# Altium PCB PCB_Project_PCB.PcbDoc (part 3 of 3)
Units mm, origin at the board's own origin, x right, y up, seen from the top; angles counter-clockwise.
Board outline 185 x 95 mm, 2 copper layers (Top Layer, Bottom Layer), stack 1.575 mm thick; 173 components, 93 nets, 424 pads, 126 vias.
Unrouted connection lines stored in the file: 1.
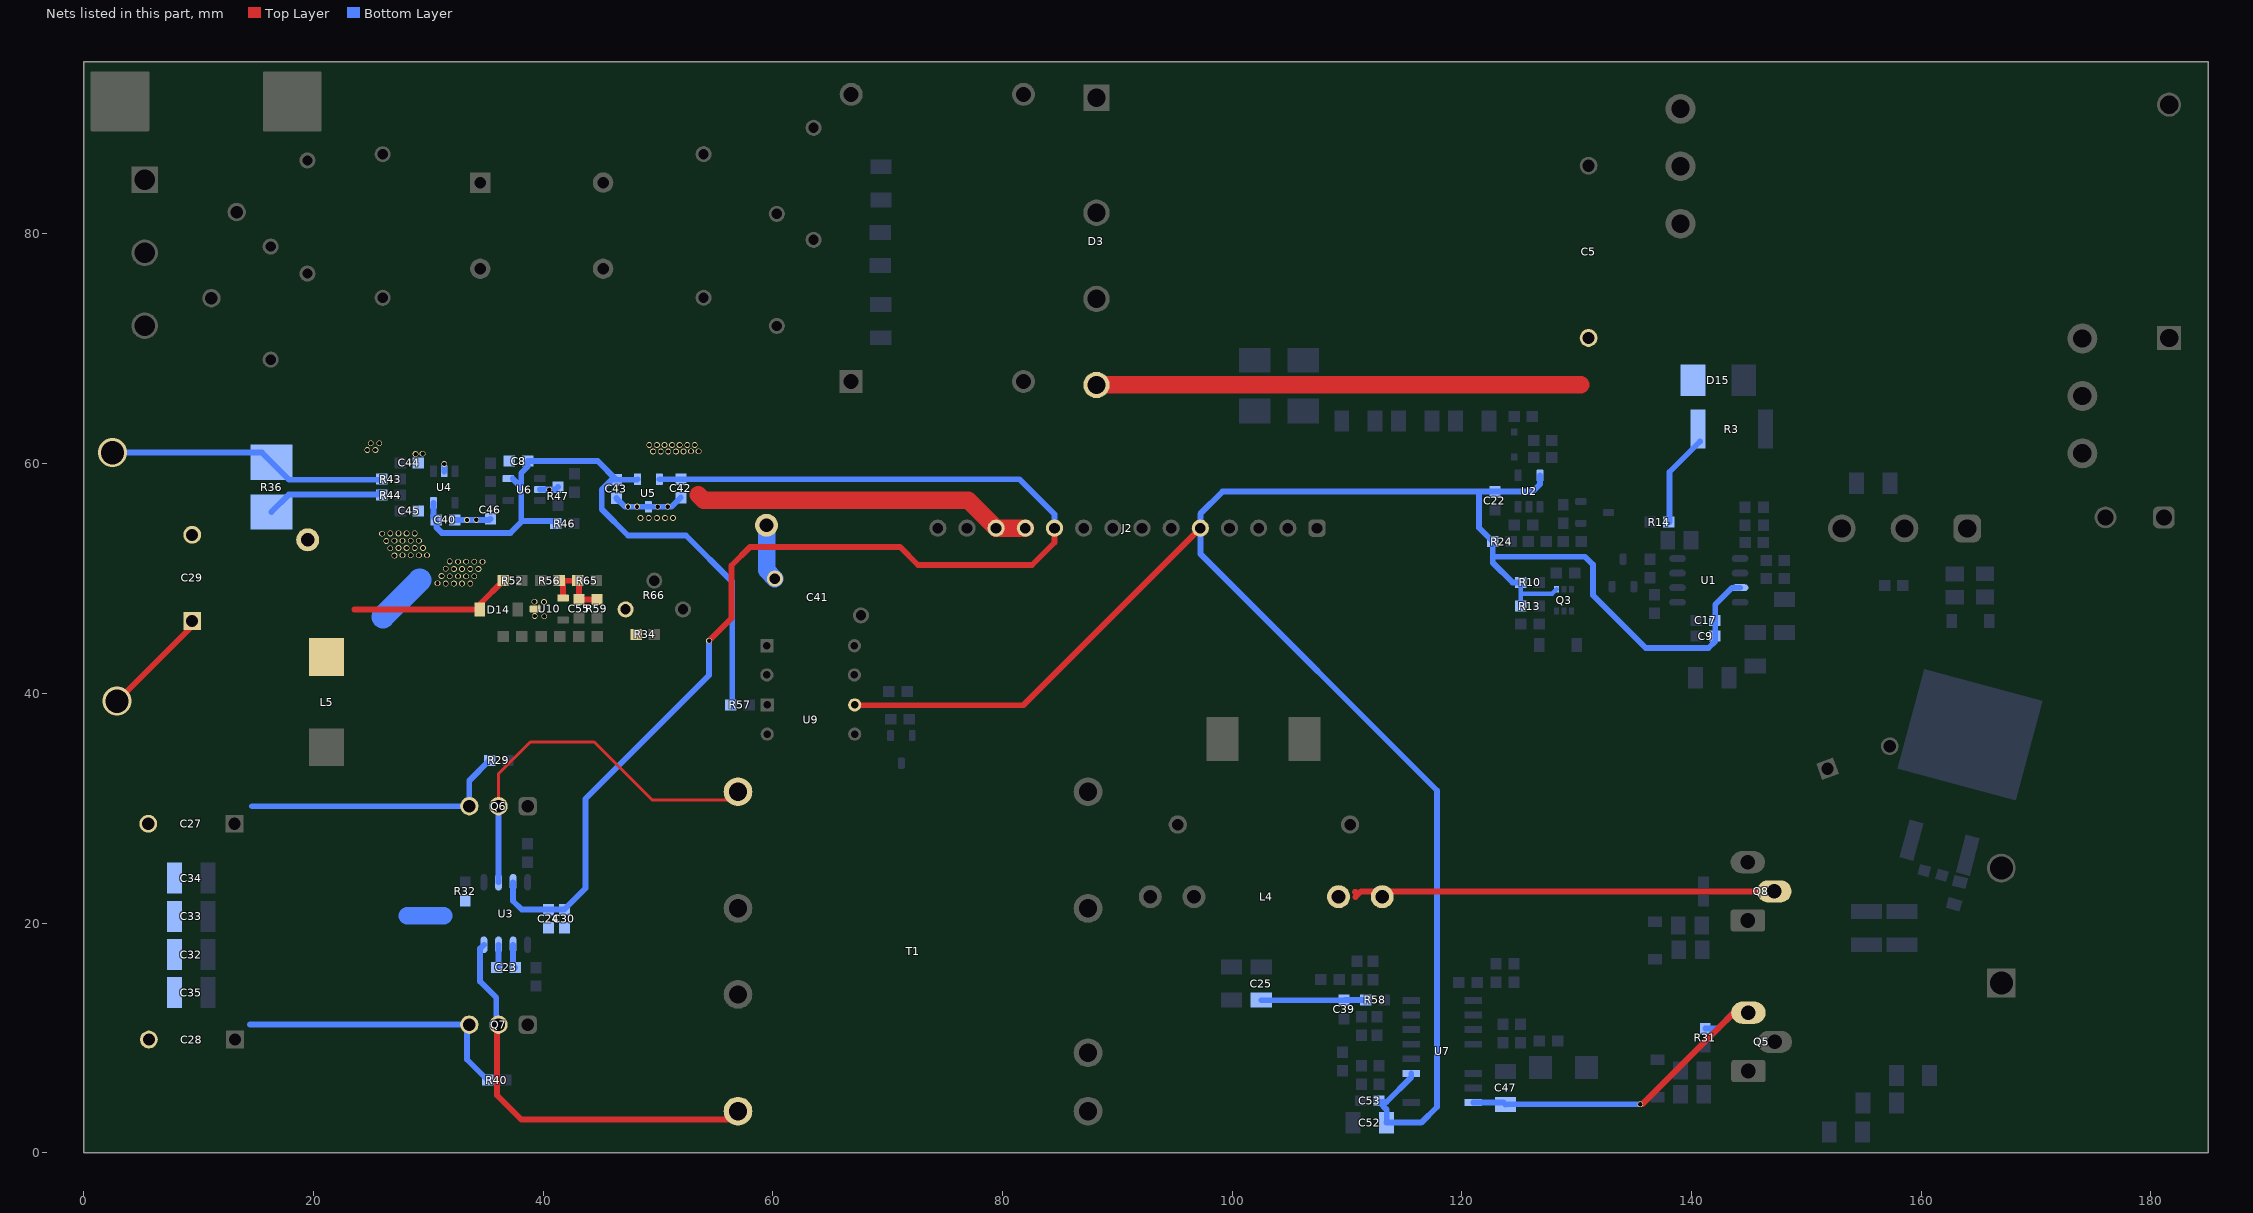
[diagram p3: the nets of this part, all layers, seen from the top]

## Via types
v1: diameter 0.508, hole 0.381, Top Layer to Bottom Layer, 124 vias
v2: diameter 2.54, hole 2.032, Top Layer to Bottom Layer, 2 vias

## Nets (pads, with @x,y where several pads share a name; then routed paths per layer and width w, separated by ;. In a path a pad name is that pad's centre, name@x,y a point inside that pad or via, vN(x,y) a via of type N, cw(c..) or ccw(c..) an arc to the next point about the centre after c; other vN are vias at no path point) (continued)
Pri_15V: C9.1 C17.1 C22.1 C52.1 C53.1 J2.5 Q3.4 R10.2 R13.2 R24.2 U1.7 U2.5 U7.3 U9.4 | length 184.7
  Top Layer w0.508: U9.4@67.142,38.964 81.813,38.964 J2.5@97.231,54.381
  Bottom Layer w0.381: R13.2@125.146,47.6 125.146,48.666 ; R10.2@125.146,49.662 125.146,48.666 ; Q3.4@128.255,49.063 127.859,48.666 125.146,48.666
  Bottom Layer w0.508: C52.1@113.439,2.616 C52.1@113.464,2.616 ; U7.3@115.592,6.909 115.592,6.575 113.436,4.42 112.789,4.42 113.464,3.744 C52.1@113.464,2.616 ; 122.695,52.019 R24.2@122.695,53.213 121.488,54.42 121.488,57.379 121.679,57.569 ; R10.2@125.146,49.662 124.404,49.662 122.695,51.371 122.695,51.892 130.734,51.892 131.42,51.206 131.42,48.539 136.017,43.942 141.478,43.942 142.075,44.539 142.075,47.739 143.535,49.199 U1.7@144.228,49.199 ; U2.5@126.807,58.982 126.807,58.202 126.174,57.569 C22.1@122.885,57.569 121.679,57.569 ; C52.1@113.464,2.616 116.459,2.616 117.831,3.988 117.831,31.547 97.231,52.146 J2.5@97.231,54.381 97.231,55.626 99.174,57.569 121.679,57.569
R_SENSE: R36.2 R43.2 | length 24.1
  Bottom Layer w0.508: v2(2.515,60.96) 15.52,60.96 R36.2@16.358,60.123 17.883,58.598 R43.2@25.654,58.598
Reg: C23.1 U3.3 | length 2
  Bottom Layer w0.508: C23.1@35.979,16.129 36.119,16.269 U3.3@36.119,18.103
Sec_3.3V: C8.1 C40.1 C43.1 R46.1 R57.2 U4.5 U5.1 U6.5 | length 58.3
  Bottom Layer w0.508: U4.5@30.444,56.575 30.444,55.357 C40.1@30.696,55.105 30.696,54.457 31.178,53.975 37.16,53.975 38.1,54.915 ; U6.5@37.353,58.697 38.1,57.95 ; R46.1@41.085,54.788 40.856,55.016 38.202,55.016 38.1,54.915 ; U5.1@48.224,58.642 48.18,58.598 C43.1@46.38,58.598 ; R57.2@56.477,38.862 56.477,49.72 52.451,53.746 47.396,53.746 45.11,56.032 45.11,57.726 45.982,58.598 C43.1@46.38,58.598 ; 38.1,54.915 38.1,57.95 ; 38.1,57.95 38.1,59.182 38.671,59.753 C8.1@38.671,60.223 44.755,60.223 C43.1@46.38,58.598
Sec_15V: C24.1 C30.1 C42.1 J2.10 U3.7 U5.2 | length 110.8
  Top Layer w0.508: v1(54.458,44.577) 56.413,46.533 56.413,51.13 58.039,52.756 71.08,52.756 72.655,51.181 82.575,51.181 84.531,53.137 J2.10@84.531,54.381
  Bottom Layer w0.508: U3.7@37.389,23.553 37.389,21.92 38.138,21.171 C24.1@40.488,21.171 41.834,21.171 43.688,23.025 43.688,30.81 54.458,41.58 v1(54.458,44.577) ; U5.2@50.124,58.642 51.987,58.642 C42.1@51.994,58.648 81.483,58.648 84.531,55.601 J2.10@84.531,54.381 J2.10@84.531,54.331
SGND: C8.2 C23.2 C24.2 C27.2 C28.2 C29.2 C30.2 C32.2 C33.2 C34.2 C35.2 C40.2 C41.2 C42.2 C43.2 C44.2 C45.2 C46.2 J2.11 J2.12 pad.2 pad.3 Q6.3 Q7.3 R29.2 R32.1 R34.1 R36.1 R40.2 R44.2 R47.1 R66.1 U3.2 U4.2 U5.3 U6.2 U10.3 | length 114.3
  Top Layer w1.524: 53.518,57.302 54,56.82 77.013,56.82 J2.12@79.451,54.381 J2.11@81.991,54.381
  Bottom Layer w0.508: 14.469,11.151 33.376,11.151 33.376,8.115 R40.2@35.166,6.325 ; 14.656,30.175 Q6.3@33.579,30.175 33.579,32.398 R29.2@35.344,34.163 ; R36.1@16.358,55.803 17.857,57.302 25.527,57.302 R44.2@25.705,57.48 ; U4.2@31.394,59.325 v1(31.394,59.969) ; C40.2@32.296,55.105 v1(34.188,55.105) 35.319,55.105 C46.2@35.408,55.194 ; U3.2@37.389,18.103 37.389,16.319 C23.2@37.579,16.129 ; U6.2@39.729,57.747 41.085,57.747 R47.1@41.3,57.963 ; C43.2@46.38,56.998 47.136,56.242 U5.3@49.174,56.242 v1(49.987,56.242) 51.187,56.242 C42.2@51.994,57.048
  Bottom Layer w1.524: 28.157,20.625 31.344,20.625 ; pad.2@59.461,54.635 59.461,50.707 C41.2@60.182,49.987
  Bottom Layer w2.007: 26.06,46.66 29.261,49.86
  other v1: 40.107,46.711 39.268,46.736 40.081,47.955 39.243,47.981 31.521,49.555 32.233,49.555 32.944,49.555 33.655,49.555 30.81,49.581 31.877,50.19 32.588,50.19 33.299,50.19 34.011,50.19 31.166,50.216 32.233,50.825 32.944,50.825 33.655,50.825 34.366,50.825 31.521,50.851 32.588,51.46 33.299,51.46 34.011,51.46 34.722,51.46 31.877,51.486 27.051,51.994 27.762,52.019 28.473,52.019 29.185,52.019 29.896,52.019 26.695,52.629 27.407,52.654 28.118,52.654 28.829,52.654 29.54,52.654 26.34,53.264 27.051,53.289 27.762,53.289 28.473,53.289 29.185,53.289 25.984,53.899 26.695,53.924 27.407,53.924 28.118,53.924 28.829,53.924 33.376,55.093 48.489,55.27 49.2,55.27 49.911,55.27 50.622,55.27 51.308,55.27 47.396,56.261 48.184,56.261 50.851,56.261 40.538,57.734 28.905,60.833 29.515,60.858 49.581,61.062 50.241,61.062 50.902,61.062 51.562,61.062 52.222,61.062 52.883,61.087 53.543,61.087 24.689,61.189 25.4,61.189 49.251,61.62 49.911,61.62 50.571,61.62 51.232,61.62 51.892,61.62 52.553,61.62 53.213,61.62 24.994,61.773 25.73,61.773
SW: C47.2 L4.1 Q5.3 Q8.2 R31.1 U7.16 | length 68.4
  Top Layer w0.508: 110.681,22.714 110.76,22.723 ; 110.735,22.266 111.227,22.758 Q8.2@147.207,22.758 ; v1(135.534,4.216) 135.712,4.216 143.688,12.192 Q5.3@144.958,12.192
  Bottom Layer w0.508: U7.16@120.992,4.369 123.624,4.369 C47.2@123.804,4.189 123.831,4.216 v1(135.534,4.216) ; R31.1@141.199,10.808 142.303,10.808 143.688,12.192 Q5.3@144.958,12.192
V42-58V: C29.1 D14.1 L5.2 R52.2 | length 24
  Top Layer w0.508: v2(2.896,39.319) 9.449,45.872 C29.1@9.449,46.304 ; 23.571,47.295 D14.1@34.507,47.295 34.507,47.778 R52.2@36.538,49.809
V_OUT: C55.1 R56.1 R59.1 R65.2 U10.2 | length 6.5
  Top Layer w0.508: U10.2@41.738,48.296 41.738,49.46 R56.1@41.389,49.809 R65.2@43.04,49.809 43.129,49.721 C55.1@43.129,48.171 R59.1@44.679,48.171
VCR: C25.2 C39.1 R58.1 | length 9.1
  Bottom Layer w0.508: C25.2@102.54,13.271 C39.1@109.758,13.271 109.796,13.31 R58.1@111.65,13.31
VD1: Q7.2 T1.7 U3.4 | length 35.8
  Top Layer w0.508: Q7.2@36.347,11.151 35.992,10.795 35.992,5.004 38.111,2.884 T1.7@56.998,2.884
  Bottom Layer w0.508: U3.4@34.849,18.103 34.519,17.773 34.519,14.91 35.916,13.513 Q7.2@35.916,11.151
VD2: Q6.2 T1.12 U3.6 | length 33.6
  Top Layer w0.254: Q6.2@36.119,30.175 36.119,32.995 38.887,35.763 44.45,35.763 49.519,30.694 T1.12@56.998,30.694
  Bottom Layer w0.508: U3.6@36.119,23.553 Q6.2@36.119,30.175
VN: C5.2 D3.4 D15.1 R3.1 R14.2 | length 50.3
  Top Layer w1.524: D3.4@88.189,66.853 130.351,66.853
  Bottom Layer w0.508: R14.2@138.085,54.915 138.085,59.269 R3.1@140.741,61.925
pads on no net: J2.2 J2.6 J2.7 J2.8 J2.9 J2.13 J2.14 R22.2 R66.3 U1.4
copper on no net: | length 1.8
  Bottom Layer w0.508: 138.138,53.315 138.138,52.38 138.778,51.739

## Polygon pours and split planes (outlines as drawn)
NetC10_2 on Top Layer "TOP_LAYER_NETC10_2_P104" (solid, pour order 104): 59.309,69.171 54.204,69.171 54.204,73.152 61.239,73.152 61.773,72.619 61.773,71.314 61.401,70.942 59.69,70.942 59.309,70.561
NetC2_1 on Top Layer "TOP_LAYER_NETC2_1_P112" (solid, pour order 112): 54.966,92.786 62.255,92.786 62.56,92.481 62.56,90.348 62.763,90.145 64.349,90.145 64.567,90.363 64.567,93.294 65.329,94.056 68.605,94.056 69.367,93.294 69.367,89.027 68.656,88.316 55.499,88.316 54.966,88.849
NetC2_1 on Top Layer "TOP_LAYER_NETC2_1_P108" (solid, pour order 108): 49.098,92.71 52.857,92.71 52.857,90.348 52.857,88.24 47.803,83.185 44.298,83.185 43.866,83.617 43.866,87.478
NetC10_2 on Top Layer "TOP_LAYER_NETC10_2_P106" (solid, pour order 106): 61.239,73.152 64.491,73.152 68.809,68.834 68.809,65.71 68.224,65.126 63.627,65.126 61.417,67.335 61.417,70.587 61.011,70.993 61.011,72.923
NetC10_2 on Top Layer "TOP_LAYER_NETC10_2_P104" (solid, pour order 104): 46.796,69.028 52.781,69.028 52.781,73.152 52.197,73.152 47.092,78.257 44.907,78.257 44.475,78.283 43.967,77.775 43.967,71.857
NetC3_2 on Top Layer "TOP_LAYER_NETC3_2_P102" (solid, pour order 102): 24.105,94.259 25.273,93.091 29.464,93.091 36.297,86.258 36.297,83.515 35.916,83.134 31.445,83.134 28.55,86.03 20.599,86.03 20.599,93.878 20.98,94.259
NetC4_2 on Top Layer "TOP_LAYER_NETC4_2_P100" (solid, pour order 100): 8.271,73.609 10.227,75.565 11.989,75.565 15.291,72.263 15.291,70.501 15.637,70.155 19.888,70.155 25.07,75.336 29.246,75.336 32.258,78.13 35.484,78.13 35.865,77.749 35.865,76.352 35.103,75.59 35.103,73.355 28.753,67.005 23.825,67.005 17.907,67.005 13.538,67.005 10.693,69.85 4.14,69.85 3.607,70.383 3.607,73.228 3.988,73.609
V42-58V on Top Layer "TOP_LAYER_V42-58V_P046" (solid, pour order 46): 0.691,41.885 0.691,36.825 1.524,35.992 5.105,35.992 5.893,36.779 5.893,41.885
V42-58V on Top Layer "TOP_LAYER_V42-58V_P044" (solid, pour order 44): 0.691,41.275 23.139,41.275 23.901,42.037 23.901,48.387 23.19,49.098 1.473,49.098 0.691,48.316
NetC27_1 on Top Layer "TOP_LAYER_NETC27_1_P042" (solid, pour order 42): 23.851,31.42 10.185,31.42 10.185,36.195 11.044,37.053 22.814,37.053 23.851,36.017
VD2 on Top Layer "TOP_LAYER_VD2_P036" (solid, pour order 36): 60.173,30.81 60.173,32.639 59.004,33.807 50.978,33.807 45.974,38.811 34.747,38.811 34.315,38.379 34.315,34.112 35.281,33.147 35.281,28.702 35.56,28.423 36.728,28.423 36.982,28.677 36.982,33.122 37.668,33.807 43.002,33.807 48.527,28.283 49.073,27.737 58.979,27.737 60.173,28.931
NetC27_1 on Top Layer "TOP_LAYER_NETC27_1_P032" (solid, pour order 32): 60.02,22.022 58.547,23.495 46.736,23.495 44.12,26.111 29.362,26.111 22.784,32.69 10.185,32.69 10.185,7.645 11.862,5.969 20.142,5.969 28.981,14.808 42.596,14.808 47.168,10.236 58.547,10.236 60.02,11.709
VD1 on Top Layer "TOP_LAYER_VD1_P028" (solid, pour order 28): 59.682,4.91 58.649,5.944 39.192,5.944 37.008,8.128 37.008,12.548 36.5,13.056 35.687,13.056 35.23,12.598 35.23,8.509 33.223,6.502 33.223,1.473 34.061,0.635 58.852,0.635 59.653,1.436
PGND on Top Layer "TOP_LAYER_PGND_P026" (solid, pour order 26): 141.046,27.254 143.866,24.435 146.939,24.435 147.904,25.4 147.904,29.921 144.297,33.528 111.201,33.528 107.086,37.643 104.902,37.643 104.902,29.413 107.061,27.254
NetC25_1 on Top Layer "TOP_LAYER_NETC25_1_P024" (solid, pour order 24): 98.501,37.795 87.808,37.795 85.496,35.484 85.496,28.778 87.122,27.153 98.019,27.153 100.508,29.642 100.508,35.789
NetL4_2 on Top Layer "TOP_LAYER_NETL4_2_P022" (solid, pour order 22): 97.194,23.749 86.157,23.749 85.141,22.733 85.141,18.593 86.512,17.221 96.19,17.221 98.196,19.228 98.196,22.867
SW on Top Layer "TOP_LAYER_SW_P020" (solid, pour order 20): 147.752,23.673 139.522,23.673 138.379,24.816 108.407,24.816 107.518,23.927 107.518,20.65 108.331,19.837 137.617,19.837 139.499,21.869 147.777,21.869 148.26,22.352 148.26,23.343 148.285,23.368
PGND on Top Layer "TOP_LAYER_PGND_P016" (solid, pour order 16): 131.75,17.678 132.69,16.739 132.69,1.118 131.953,0.381 107.823,0.381 106.756,1.448 106.756,15.977 108.458,17.678
SW on Top Layer "TOP_LAYER_SW_P014" (solid, pour order 14): 146.406,23.698 150.952,23.698 152.222,22.428 152.222,12.776 150.8,11.354 143.104,11.354 142.57,11.887 142.57,14.249 143.243,14.922 146.672,14.922 148.285,16.535 148.285,21.336 147.828,21.793 146.456,21.793 145.898,22.352 145.898,23.19
PGND on Top Layer "PGND" (solid, pour order 0): 121.209,43.739 147.853,43.739 149.073,44.958 149.073,56.871 146.812,59.131 121.056,59.131 120.777,58.852 120.777,44.018
SGND on Top Layer "TOP_LAYER_SGND_P056" (solid, pour order 56): 24.613,62.255 23.876,61.519 23.876,53.95 25.629,52.197 53.746,52.197 54.585,53.035 54.585,61.417 53.746,62.255
SGND on Top Layer "TOP_LAYER_SGND_P058" (solid, pour order 58): 54.585,53.035 54.585,45.771 51.714,42.901 34.925,42.901 25.451,52.375 26.111,53.035
NetF1_2 on Top Layer "TOP_LAYER_NETF1_2_P070" (solid, pour order 70): 0.406,94.361 0.406,83.998 1.245,83.16 6.68,83.16 7.544,84.023 7.544,86.665 6.401,87.808 6.401,93.243 5.283,94.361
NetC3_2 on Top Layer "TOP_LAYER_NETC3_2_P072" (solid, pour order 72): 12.04,82.017 12.04,83.972 15.062,86.995 15.062,93.878 15.443,94.259 21.539,94.259 21.539,87.071 15.392,80.924 12.04,80.924
NetD3_2 on Top Layer "TOP_LAYER_NETD3_2_P076" (solid, pour order 76): 83.16,93.624 83.16,86.309 85.674,83.795 89.459,83.795 89.865,83.388 89.865,80.67 89.459,80.264 83.922,80.264 79.756,84.43 79.756,93.853 80.137,94.234 82.753,94.234 83.16,93.828
NetD3_3 on Top Layer "TOP_LAYER_NETD3_3_P078" (solid, pour order 78): 89.891,75.971 83.058,75.971 79.578,72.492 79.578,65.634 80.518,64.694 82.474,64.694 83.21,65.43 83.21,70.79 84.938,72.517 89.23,72.517 89.891,73.177
NetC5_1 on Top Layer "TOP_LAYER_NETC5_1_P086" (solid, pour order 86): 135.788,94.005 135.788,88.341 87.732,88.341 86.563,89.51 86.563,93.675 86.893,94.005
VN on Top Layer "TOP_LAYER_VN_P088" (solid, pour order 88): 125.934,68.478 129.312,71.857 132.105,71.857 133.858,70.104 133.858,64.872 132.69,63.703 87.909,63.703 86.843,64.77 86.843,68.072 87.249,68.478
NetC5_1 on Top Layer "TOP_LAYER_NETC5_1_P092" (solid, pour order 92): 135.788,94.005 142.875,94.005 143.916,92.964 143.916,78.664 143.154,77.902 136.779,77.902 135.738,78.943 129.616,85.065 129.616,94.005
NetC5_1 on Top Layer "TOP_LAYER_NETC5_1_P094" (solid, pour order 94): 142.875,94.005 183.007,94.005 184.404,92.608 184.404,89.967 183.667,89.23 142.9,89.23 142.875,89.256
NetC13_1 on Top Layer "TOP_LAYER_NETC13_1_P096" (solid, pour order 96): 176.784,71.526 176.784,68.428 177.47,67.742 177.47,53.645 176.784,52.959 171.856,52.959 171.247,53.569 171.247,73.203 171.806,73.762 176.403,73.762 176.84,73.324 176.84,73.127
NetC13_1 on Top Layer "TOP_LAYER_NETC13_1_P098" (solid, pour order 98): 159.436,52.502 160.096,53.162 160.096,56.744 161.823,58.471 171.679,58.471 172.695,59.487 172.695,63.627 171.78,64.541 156.794,64.541 155.346,63.094 155.346,57.988 156.921,56.413 156.921,53.181 157.635,52.502
PGND on Bottom Layer "BOTTOM_LAYER_PGND_P116" (solid, pour order 116): 160.274,28.575 160.274,30.746 156.972,31.598 155.067,33.249 154.498,33.818 154.498,36.489 157.251,39.243 157.251,50.063 154.661,52.654 154.661,59.512 150.52,59.512 150.52,41.25 143.967,34.696 143.916,34.696 142.443,33.223 142.443,25.832 143.764,24.511 150.165,24.511 150.673,24.003 150.673,20.98 151.308,20.345 159.995,20.345 160.274,20.625
PGND on Bottom Layer "BOTTOM_LAYER_PGND_P114" (solid, pour order 114): 137.498,47.498 136.703,47.498 136.304,47.099 136.304,46.22 136.652,45.872 140.894,45.872 140.97,45.949 140.97,48.489 139.725,48.489 139.497,48.26 138.26,48.26
VN on Bottom Layer "BOTTOM_LAYER_VN_P090" (solid, pour order 90): 141.199,68.809 137.998,72.009 128.626,72.009 128.626,66.091 133.299,61.417 141.199,61.417
R_SENSE on Bottom Layer "BOTTOM_LAYER_R_SENSE_P050" (solid, pour order 50): 18.263,58.649 18.263,63.17 0.406,63.17 0.406,58.649
SGND on Bottom Layer "BOTTOM_LAYER_SGND_P048" (solid, pour order 48): 24.257,49.835 17.221,56.871 1.228,56.871 0.66,56.202 0.66,49.835
SGND on Bottom Layer "BOTTOM_LAYER_SGND_P040" (solid, pour order 40): 42.113,27.026 42.875,26.264 42.875,15.418 42.215,14.757 37.262,14.757 31.852,14.757 30.988,15.621 30.988,25.806 32.207,27.026
SGND on Bottom Layer "BOTTOM_LAYER_SGND_P038" (solid, pour order 38): 34.417,12.09 33.706,12.802 30.48,12.802 28.905,14.376 28.905,26.695 30.785,28.575 33.985,28.575 34.417,29.007 34.417,39.7 24.028,50.089 0.457,50.089 0.457,1.245 0.914,0.787 33.909,0.787 34.417,1.295
390V on Bottom Layer "BOTTOM_LAYER_390V_P012" (solid, pour order 12): 184.455,62.205 184.607,62.052 184.607,10.693 182.601,8.687 161.468,8.687 159.817,10.338 159.817,16.866 153.949,16.866 153.619,16.535 153.619,9.398 152.908,8.687 146.507,8.687 145.923,9.271 145.923,10.185 146.431,10.693 147.879,10.693 148.895,11.709 148.895,17.577 149.962,18.644 170.815,18.644 174.041,21.869 174.041,49.987 177.978,49.987 179.832,51.841 179.832,61.773 180.264,62.205
SGND on Bottom Layer "BOTTOM_LAYER_SGND_P052" (solid, pour order 52): 34.417,33.655 34.417,39.497 30.429,43.485 23.724,43.485 22.809,42.57 31.725,33.655 31.801,33.655
SGND on Bottom Layer "BOTTOM_LAYER_SGND_P054" (solid, pour order 54): 24.613,62.255 53.746,62.255 54.585,61.417 54.585,53.035 53.746,52.197 25.629,52.197 23.876,53.95 23.876,61.519 24.282,61.925
SGND on Bottom Layer "BOTTOM_LAYER_SGND_P060" (solid, pour order 60): 54.585,53.035 54.585,45.771 51.714,42.901 34.925,42.901 24.79,53.035
PGND on Bottom Layer "BOTTOM_LAYER_PGND_P064" (solid, pour order 64): 154.661,60.808 150.749,64.719 145.694,64.719 145.694,60.935 148.158,58.471 154.457,58.471 154.661,58.674
PGND on Bottom Layer "BOTTOM_LAYER_PGND_P066" (solid, pour order 66): 147.65,58.979 151.206,55.423 151.206,58.979
390V on Bottom Layer "BOTTOM_LAYER_390V_P084" (solid, pour order 84): 184.394,72.527 183.54,73.381 180.721,73.381 179.857,72.517 179.857,61.722 180.137,61.443 183.998,61.443 184.394,61.722

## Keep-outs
Keep-Out Layer:
  the board outline again, w0.1
  text ".Layer_Name" at 14.656,-21.806 h0.7

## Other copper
Top Layer:
  text ".Layer_Name" at 14.656,-21.806 h0.7
Bottom Layer:
  text ".Layer_Name" at 14.656,-21.806 h0.7

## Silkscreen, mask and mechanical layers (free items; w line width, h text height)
Top Overlay:
  lines w0.508: 19.253,53.416 19.507,53.416 20.726,54.635 ; 20.498,54.585 20.625,54.712 59.258,54.712
  text ".Layer_Name" at 14.656,-21.806 h0.7
Bottom Overlay:
  text ".Layer_Name" at 14.656,-21.806 h0.7
Top Paste:
  text ".Layer_Name" at 14.656,-21.806 h0.7
Bottom Paste:
  text ".Layer_Name" at 14.656,-21.806 h0.7
Top Solder:
  text ".Layer_Name" at 14.656,-21.806 h0.7
  text ".Layer_Name" at 14.656,-21.806 h0.7
Bottom Solder:
  text ".Layer_Name" at 14.656,-21.806 h0.7
Drill Guide:
  text ".Layer_Name" at 14.656,-21.806 h0.7
M1 Board Outline:
  the board outline again, w0.254
  text ".Layer_Name" at 14.656,-21.806 h0.7
M2 Board Dimensions:
  rectangle: 3.175,-10.16 12.7,-6.985
  rectangle: 0,-6.985 3.175,-3.81
  lines w0.178: 0,-6.985 25.4,-6.985 ; 3.175,-10.16 3.175,-3.81 ; 6.35,-10.16 6.35,-3.81 ; 12.7,-10.16 12.7,-3.81 ; 19.05,-10.16 19.05,-3.81 ; 0,-10.16 0,-3.81 25.4,-3.81 25.4,-10.16 0,-10.16
  text ".Layer_Name" at 14.656,-21.806 h0.7
M3 3D STEP Top:
  text ".Layer_Name" at 14.656,-21.806 h0.7
M4 3D STEP Bottom:
  text ".Layer_Name" at 14.656,-21.806 h0.7
M5 Assembly Top:
  lines w0.254: -7.417,-23.626 160.223,-23.626 ; -7.417,-18.462 160.274,-18.462 ; -7.417,-13.297 -7.417,-28.791 94.31,-28.791 160.274,-28.791 160.274,-13.297 -7.404,-13.297 -7.404,-28.791 32.614,-28.791 ; 55.194,-28.791 55.194,-13.297 ; 87.376,-18.462 87.376,-13.297 ; 108.712,-18.462 108.712,-13.297 ; 124.511,-28.956 124.511,-23.804
  text "COMPONENTS MARKED 'DNP' SHOULD NOT BE POPULATED." at 29.299,-8.09 h0.7
  text "ASSEMBLY VARIANT:" at 29.286,-11.024 h0.7
  text ".VariantName" at 55.601,-11.024 h0.7
  text "PCB VIEWED FROM TOP SIDE" at -5.804,-16.654 h0.7
  text "BOARD #:" at 57.099,-16.654 h0.7
  text ".PRJ_Number" at 70.955,-16.654 h0.7
  text "REV:" at 92.405,-16.654 h0.7
  text ".PCB_Rev" at 99.809,-16.654 h0.7
  text "SVN REV:" at 113.69,-16.654 h0.7
  text ".VersionControl_RevNumber" at 126.543,-16.654 h0.7
  text "TID #:" at 57.099,-21.819 h0.7
  text ".TID" at 70.955,-21.819 h0.7
  text "PLOT NAME =" at -5.804,-27.034 h0.7
  text ".plot_File_Name" at 14.656,-27.034 h0.7
  text "GENERATED    :" at 57.15,-27.034 h0.7
  text ".Print_Date" at 79.235,-27.034 h0.7
  text ".Print_Time" at 97.752,-27.034 h0.7
  text "TEXAS INSTRUMENTS" at 129.87,-27.034 h0.7
M6 Assembly Bottom:
  lines w0.254: -7.429,-18.474 160.261,-18.474 ; -7.379,-23.639 160.261,-23.639 ; 28.334,-28.969 28.334,-23.817 ; 44.133,-18.474 44.133,-13.31 ; 65.468,-18.474 65.468,-13.31 ; 97.65,-28.804 97.65,-13.31 ; 120.231,-28.804 160.249,-28.804 160.249,-13.31 -7.429,-13.31 -7.429,-28.804 58.534,-28.804 160.261,-28.804 160.261,-13.31
  text "COMPONENTS MARKED 'DNP' SHOULD NOT BE POPULATED." at 154.991,-8.077 h0.7
  text ".VariantName" at 128.473,-11.024 h0.7
  text "ASSEMBLY VARIANT:" at 154.864,-11.024 h0.7
  text ".VersionControl_RevNumber" at 26.302,-16.667 h0.7
  text "SVN REV:" at 39.154,-16.667 h0.7
  text ".PCB_Rev" at 53.035,-16.667 h0.7
  text "REV:" at 60.439,-16.667 h0.7
  text ".PRJ_Number" at 81.89,-16.667 h0.7
  text "BOARD #:" at 95.745,-16.667 h0.7
  text "PCB VIEWED FROM BOTTOM SIDE" at 158.648,-16.667 h0.7
  text ".TID" at 81.89,-21.831 h0.7
  text "TID #:" at 95.745,-21.831 h0.7
  text "TEXAS INSTRUMENTS" at 22.974,-27.047 h0.7
  text ".Print_Time" at 55.093,-27.047 h0.7
  text ".Print_Date" at 73.609,-27.047 h0.7
  text "GENERATED    :" at 95.694,-27.047 h0.7
  text ".plot_File_Name" at 138.189,-27.047 h0.7
  text "PLOT NAME =" at 158.648,-27.047 h0.7
M9 Title Sheet:
  drawing of 57 lines, arcs and shapes, not listed
  text "1" at 18.792,204.127 h1.78
  text "2" at 82.182,204.127 h1.78
  text "3" at 145.411,204.127 h1.78
  text "4" at 209.08,204.127 h1.78
  text "5" at 272.555,204.127 h1.78
  text "6" at 336.182,204.127 h1.78
  text "A" at -10.579,175.095 h1.78
  text "A" at 365.341,175.095 h1.78
  text "B" at -10.579,114.643 h1.78
  text "B" at 365.341,114.643 h1.78
  text "C" at -10.579,54.318 h1.78
  text "C" at 365.341,54.318 h1.78
  text "PROJECT TITLE:" at 288.125,7.048 h1.14
  text ".PRJ_Title" at 289.395,3.662 h1.78
  text "DESIGNED FOR:" at 288.125,-0.597 h1.14
  text ".PRJ_Customer" at 289.395,-4.153 h1.78
  text "D" at -10.579,-5.88 h1.78
  text "D" at 365.341,-5.88 h1.78
  text "FILE NAME:" at 288.125,-8.217 h1.14
  text ".PCB_File_Name_No_Path" at 289.395,-11.265 h1.78
  text "Texas Instruments (TI) and/or its licensors do not warrant the accuracy or completeness of this specification" at 161.9,-15.376 h1.14
  text "ENGINEER:" at 288.125,-15.583 h1.14
  text "LAYOUT BY:" at 326.352,-15.583 h1.14
  text "or any information contained therein. TI and/or its licensors do not warrant that this design will meet" at 160.757,-18.237 h1.14
  text ".PRJ_Engineer" at 289.395,-19.52 h1.78
  text ".PCB_Layout" at 327.635,-19.52 h1.78
  text "the specifications, will be suitable for your application or fit for any particular purpose, or will operate in" at 160.757,-21.099 h1.14
  text ".Layer_Name" at 14.656,-21.806 h0.7
  text "ALTIUM DESIGNER VERSION:" at 326.352,-23.457 h1.14
  text "an implementation. TI and/or its licensors do not warrant that the design is production worthy. You should" at 160.757,-23.961 h1.14
  text "completely validate and test your design implementation to confirm the system functionality for your application." at 161.9,-26.822 h1.14
  text ".print_Scale" at 289.395,-26.843 h1.78
  text ".Application_BuildNumber" at 327.635,-26.843 h1.78
  text "1" at 18.792,-32.093 h1.78
  text "2" at 82.182,-32.093 h1.78
  text "3" at 145.411,-32.093 h1.78
  text "4" at 209.08,-32.093 h1.78
  text "5" at 272.555,-32.093 h1.78
  text "6" at 336.182,-32.093 h1.78
M10 Fab Notes:
  drawing of 189 lines, arcs and shapes, not listed
  text "DESIGN INFORMATION" at 314.503,161.447 h0.7
  text "MIN. TRACK WIDTH:" at 298.131,158.091 h0.7
  text "8" at 325.976,158.091 h0.7
  text "MIL" at 329.907,158.091 h0.7
  text "MIN. CLEARANCE:" at 298.131,154.938 h0.7
  text "0.2" at 324.452,154.938 h0.7
  text "mm" at 329.907,154.938 h0.7
  text "MIN. VIA PAD SIZE:" at 298.131,151.785 h0.7
  text "24" at 325.214,151.785 h0.7
  text "MIL" at 329.907,151.785 h0.7
  text "0.05mm (2MIL)" at 315.784,148.486 h0.7
  text "MINIMUM ANNULAR RING" at 289.769,148.277 h0.7
  text "EXTERNAL" at 333.768,148.277 h0.7
  text "PER" at 294.849,145.48 h0.7
  text "IPC-D-275 CLASS 2 LEVEL C" at 300.437,145.48 h0.7
  text "MIL, HOLES" at 338.238,142.928 h0.7
  text "+/-" at 328.27,142.709 h0.7
  text "+/-" at 349.961,142.709 h0.7
  text "REGISTRATION TOLERANCES:" at 289.769,142.682 h0.7
  text "METAL" at 320.243,142.682 h0.7
  text "5" at 334.879,142.683 h0.7
  text "3" at 356.037,142.683 h0.7
  text "MIL" at 358.99,142.682 h0.7
  text "HOLE SIZE TOLERANCE (UNLESS OTHERWISE SPECIFIED):" at 289.769,140.185 h0.7
  text "+/-" at 349.961,140.112 h0.7
  text "3" at 356.037,140.085 h0.7
  text "MIL" at 358.99,140.085 h0.7
  text "MATERIAL:" at 287.87,136.589 h0.7
  text "FR-4 High Tg" at 312.926,133.324 h0.7
  text "X" at 309.257,133.122 h0.7
  text "FR-408" at 298.563,133.007 h0.7
  text "OTHER" at 336.358,133.007 h0.7
  text "62 MIL (1.6mm) +/-10%" at 306.694,129.374 h0.7
  text "X" at 303.643,129.312 h0.7
  text "THICKNESS:" at 289.769,129.165 h0.7
  text "OTHER" at 339.33,129.165 h0.7
  text "TOLERANCE:" at 289.769,125.652 h0.7
  text "X" at 311.314,125.652 h0.7
  text "ANSI IPC-6012 TYPE 3 CLASS 2" at 315.836,125.652 h0.7
  text "OTHER +/-" at 315.835,121.989 h0.7
  text "BOW & TWIST:" at 289.769,118.302 h0.7
  text "X" at 311.314,118.302 h0.7
  text "ANSI IPC-6012 TYPE 3 CLASS 2" at 315.836,118.302 h0.7
  text "OTHER +/-" at 315.835,114.576 h0.7
  text "DRILLING:" at 287.87,111.258 h0.7
  text "NC_DRILL FILES" at 332.599,108.586 h0.7
  text "REFERENCE:" at 289.769,108.486 h0.7
  text "X" at 306.463,108.484 h0.7
  text "AS SHOWN" at 310.984,108.486 h0.7
  text "X" at 329.348,108.486 h0.7
  text "OTHER" at 340.168,104.873 h0.7
  text "PTH COPPER THICKNESS:" at 289.761,104.783 h0.7
  text "X" at 318.697,104.783 h0.7
  text "20-30 um" at 321.948,104.783 h0.7
  text "BOARD FINISH:" at 287.87,101.034 h0.7
  text "SILKSCREEN:" at 291.812,98.237 h0.7
  text "X" at 316.14,98.237 h0.7
  text "TOP" at 319.112,98.237 h0.7
  text "X" at 329.094,98.237 h0.7
  text "BOTTOM" at 332.091,98.237 h0.7
  text "SILKSCREEN COLOR:" at 291.812,94.295 h0.7
  text "X" at 316.115,94.295 h0.7
  text "WHITE" at 319.112,94.295 h0.7
  text "OTHER" at 332.091,94.295 h0.7
  text "X" at 319.442,90.652 h0.7
  text "GREEN" at 322.439,90.652 h0.7
  text "OTHER" at 338.136,90.652 h0.7
  text "SOLDER RESIST COLOR:" at 291.812,90.477 h0.7
  text "X" at 319.442,86.734 h0.7
  text "MATTE" at 322.439,86.734 h0.7
  text "SEMI-GLOSS" at 338.125,86.717 h0.7
  text "IMMERSION GOLD (ENIG)" at 314.819,82.345 h0.7
  text "ENEPIG" at 348.793,82.162 h0.7
  text "SURFACE FINISH:" at 287.87,82.136 h0.7
  text "X" at 310.298,82.136 h0.7
  text "IMM. TIN/SILVER OR EQUIV" at 296.24,78.649 h0.7
  text "OTHER" at 332.599,78.549 h0.7
  text "ARRAY/PANEL:" at 287.87,74.602 h0.7
  text "CUT AND TRIM PER M1 BOARD OUTLINE" at 314.819,74.393 h0.7
  text "N.C. ROUTE" at 314.819,70.94 h0.7
  text "X" at 332.295,70.94 h0.7
  text "V. SCORE" at 336.816,70.94 h0.7
  text "CERTIFICATION:" at 287.87,67.66 h0.7
  text "MATERIALS AND WORKMANSHIP FOR ALL PCBS" at 306.285,67.66 h0.7
  text "TO MEET OR EXCEED THE REQUIREMENTS OF:" at 306.285,65.271 h0.7
  text "X" at 297.078,62.003 h0.7
  text "ANSI IPC-A-600F CLASS ->" at 300.329,62.003 h0.7
  text "X" at 342.188,62.003 h0.7
  text "2" at 344.982,62.003 h0.7
  text "1" at 336.981,61.965 h0.7
  text "3" at 353.973,61.965 h0.7
  text "X" at 317.702,58.252 h0.7
  text "RoHS" at 320.953,58.252 h0.7
  text "OTHER" at 337.321,58.252 h0.7
  text "PER ORDER" at 347.407,58.252 h0.7
  text "ALL BOARDS MUST MEET OR EXCEED UL94-V0 REQUIREMENTS." at 288.569,54.345 h0.7
  text "PCB MUST BEAR THE UL94V-0 UL REGISTERED MATERIAL ID NUMBER" at 288.569,51.397 h0.7
  text "ADDITIONAL REQUIREMENTS:" at 287.87,47.094 h0.7
  text "MICROSECTION:" at 289.769,44.373 h0.7
  text "YES" at 312.775,44.373 h0.7
  text "REQUIRED" at 334.657,40.707 h0.7
  text "BARE BOARD ELEC. TEST:" at 289.769,40.634 h0.7
  text "NONE" at 322.935,40.634 h0.7
  text "X" at 331.66,40.634 h0.7
  text "PER ORDER" at 349.693,40.634 h0.7
  text "XX MIL VIAS REQUIRE NON-CONDUCTIVE FILL AND PLANARIZE" at 294.04,35.428 h1.5
  text "XX MIL VIAS REQUIRE CONDUCTIVE FILL AND PLANARIZE" at 294.243,32.787 h0.7
  text "OUTER XX MIL TRACES REQUIRE 50 OHM SINGLE-ENDED IMPEDANCE" at 294.218,28.637 h1.47
  text "LAYER 2 & 3 (INNER LAYERS) XX MIL WIDE, XX MIL SPACE / TRACES REQUIRE 100 OHM DIFFERENTIAL IMPEDANCE" at 294.015,22.65 h0.7
  text ".Layer_Name" at 14.656,-21.806 h0.7
M11 Gerber Information:
  lines w0.254: -7.417,-23.626 160.223,-23.626 ; -7.417,-18.462 160.274,-18.462 ; -7.417,-13.297 -7.417,-28.791 94.31,-28.791 160.274,-28.791 160.274,-13.297 -7.404,-13.297 -7.404,-28.791 32.614,-28.791 ; 55.194,-28.791 55.194,-13.297 ; 87.376,-18.462 87.376,-13.297 ; 108.712,-18.462 108.712,-13.297 ; 124.511,-28.956 124.511,-23.804
  text "ALL ARTWORK VIEWED FROM TOP SIDE" at -5.804,-16.654 h0.7
  text "BOARD #:" at 57.099,-16.654 h0.7
  text ".PRJ_Number" at 70.955,-16.654 h0.7
  text "REV:" at 92.405,-16.654 h0.7
  text ".PCB_Rev" at 99.809,-16.654 h0.7
  text "SVN REV:" at 113.69,-16.654 h0.7
  text ".VersionControl_RevNumber" at 126.543,-16.654 h0.7
  text "LAYER NAME =" at -5.804,-21.806 h0.7
  text "TID #:" at 57.099,-21.819 h0.7
  text ".TID" at 70.955,-21.819 h0.7
  text "PLOT NAME =" at -5.804,-27.034 h0.7
  text ".plot_File_Name" at 14.656,-27.034 h0.7
  text "GENERATED    :" at 57.15,-27.034 h0.7
  text ".Print_Date" at 79.235,-27.034 h0.7
  text ".Print_Time" at 97.752,-27.034 h0.7
  text "TEXAS INSTRUMENTS" at 129.87,-27.034 h0.7
M12 Stackup:
  drawing of 191 lines, arcs and shapes, not listed
  text "Layer" at 248.041,199.892 h0.7
  text "Name" at 252.79,199.892 h0.7
  text "Material" at 263.604,199.892 h0.7
  text "Thickness" at 273.601,199.892 h0.7
  text "Constant" at 281.149,199.892 h0.7
  text "Board Layer Stack" at 287.764,199.892 h0.7
  text "1" at 248.041,198.492 h0.7
  text "Top Overlay" at 252.79,198.492 h0.7
  text "2" at 248.041,197.092 h0.7
  text "Top Solder" at 252.79,197.092 h0.7
  text "Solder Resist" at 263.604,197.092 h0.7
  text "0.40mil" at 273.601,197.092 h0.7
  text "3.5" at 281.149,197.092 h0.7
  text "3" at 248.041,195.692 h0.7
  text "Top Layer" at 252.79,195.692 h0.7
  text "Copper" at 263.604,195.692 h0.7
  text "1.40mil" at 273.601,195.692 h0.7
  text "4" at 248.041,194.292 h0.7
  text "Dielectric1" at 252.79,194.292 h0.7
  text "FR-4" at 263.604,194.292 h0.7
  text "59.20mil" at 273.601,194.292 h0.7
  text "4.8" at 281.149,194.292 h0.7
  text "5" at 248.041,192.892 h0.7
  text "Bottom Layer" at 252.79,192.892 h0.7
  text "Copper" at 263.604,192.892 h0.7
  text "1.40mil" at 273.601,192.892 h0.7
  text "6" at 248.041,191.492 h0.7
  text "Bottom Solder" at 252.79,191.492 h0.7
  text "Solder Resist" at 263.604,191.492 h0.7
  text "0.40mil" at 273.601,191.492 h0.7
  text "3.5" at 281.149,191.492 h0.7
  text "7" at 248.041,190.092 h0.7
  text "Bottom Overlay" at 252.79,190.092 h0.7
  text ".Layer_Name" at 14.656,-21.806 h0.7
M13 Component Bodies Top:
  text ".Layer_Name" at 14.656,-21.806 h0.7
M14 Component Bodies Bottom:
  text ".Layer_Name" at 14.656,-21.806 h0.7
M15 Courtyards Top:
  text ".Layer_Name" at 14.656,-21.806 h0.7
M16 Courtyards Bottom:
  text ".Layer_Name" at 14.656,-21.806 h0.7
Drill Drawing:
  text ".Layer_Name" at 14.656,-21.806 h0.7
M17 Embedded Cavity:
  text ".Layer_Name" at 14.656,-21.806 h0.7
M18 Embedded Assembly:
  text ".Layer_Name" at 14.656,-21.806 h0.7
M19 Embedded Keepout:
  text ".Layer_Name" at 14.656,-21.806 h0.7

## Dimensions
0,0 to 185,0 on M2 Board Dimensions
0,0 to 0,95 on M2 Board Dimensions
0,-10.16 to 25.4,-10.16 on M2 Board Dimensions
